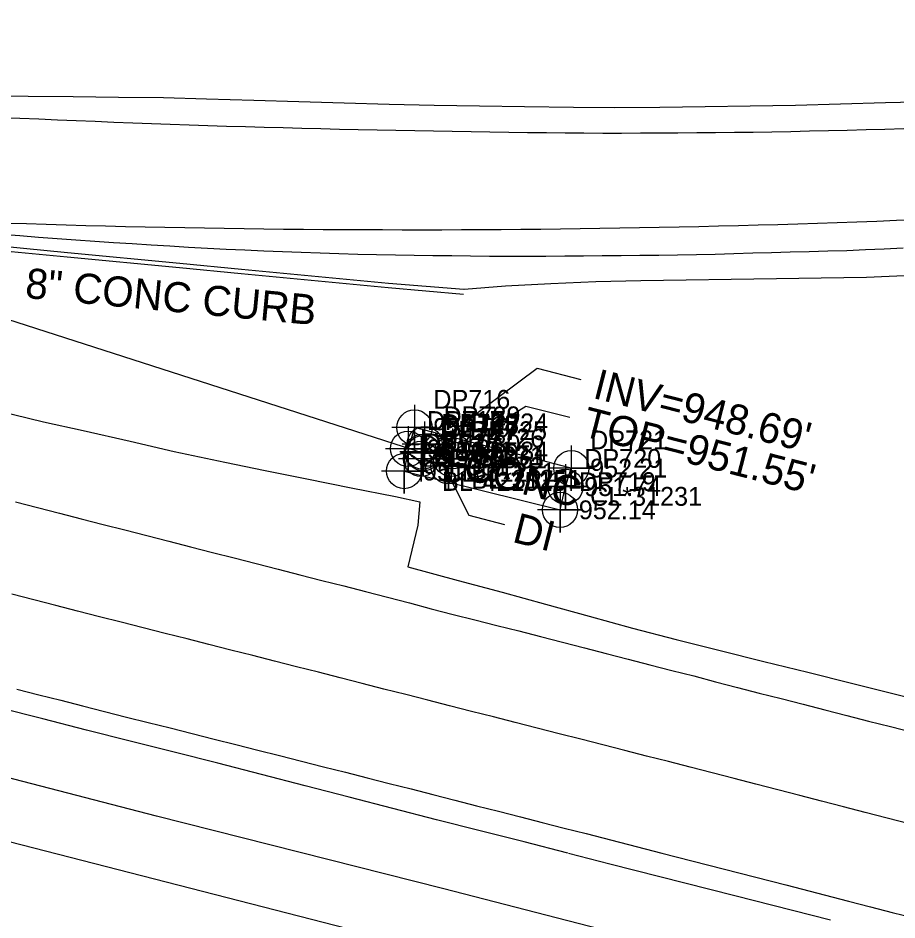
# Model space of a CAD drawing. Extents: x 1182322 to 1186765, y 572295 to 575411.
# Drawn here: x 1183843.1 to 1183959.9, y 574241.7 to 574361.5 of the extents above; entities that cross this region are included whole.
import ezdxf

# ---------------------------------------------------------------- set-up
doc = ezdxf.new("R2010")
doc.units = 0
for name, color, linetype in [('COGO Default Chain', 7, 'Continuous'), ('Exist Guardrail Cable Guide Rail', 7, 'Continuous'), ('Exist Horizontal Alignment', 7, 'Continuous'), ('Exist Right of Way Line', 7, 'Continuous'), ('Exist Roads Curbs', 7, 'Continuous'), ('Exist Roads Curbs Text', 7, 'Continuous'), ('Exist Roads EOP', 7, 'Continuous'), ('Exist Roads EOT', 7, 'Continuous'), ('Exist Structure Minor Drop Inlet', 7, 'Continuous'), ('Exist Structure Minor Drop Inlet Cogo Comment', 7, 'Continuous'), ('Exist Structure Minor Drop Inlet Cogo Elevation', 7, 'Continuous'), ('Exist Structure Minor Drop Inlet Cogo Number', 7, 'Continuous'), ('Exist Structure Minor Drop Inlet Cogo Point CELL', 7, 'Continuous'), ('Exist Structure Minor Drop Inlet Leader', 7, 'Continuous'), ('Exist Structure Minor Drop Inlet Text', 7, 'Continuous'), ('Exist Structure Minor Drop Inlet Top Elevation', 7, 'Continuous'), ('Exist Structure Minor Paved Ditch or Gutter', 7, 'Continuous'), ('Exist Structure Minor Paved Ditch or Gutter Cogo Comment', 7, 'Continuous'), ('Exist Structure Minor Paved Ditch or Gutter Cogo Elevation', 7, 'Continuous'), ('Exist Structure Minor Paved Ditch or Gutter Cogo Number', 7, 'Continuous'), ('Exist Structure Minor Paved Ditch or Gutter Cogo Point CELL', 7, 'Continuous'), ('Exist Structure Minor Paved Ditch or Gutter Text', 7, 'Continuous'), ('Exist Structure Minor Pipes RCP 15 Inch', 7, 'Continuous'), ('Exist Structure Minor Pipes RCP 15 Inch Cogo Comment', 7, 'Continuous'), ('Exist Structure Minor Pipes RCP 15 Inch Cogo Elevation', 7, 'Continuous'), ('Exist Structure Minor Pipes RCP 15 Inch Cogo Number', 7, 'Continuous'), ('Exist Structure Minor Pipes RCP 15 Inch Cogo Point CELL', 7, 'Continuous'), ('Exist Structure Minor Pipes RCP 15 Inch Invert', 7, 'Continuous'), ('Exist Structure Minor Pipes RCP 15 Inch Leader', 7, 'Continuous')]:
    doc.layers.add(name, color=color, linetype=linetype)

msp = doc.modelspace()

# ---------------------------------------------------------------- linework, layer by layer
at = {"layer": 'COGO Default Chain'}
msp.add_line((1182528.88, 574588.22), (1185362.14, 573862.9), dxfattribs=at)
msp.add_arc((1183895.74, 575980.86), 1647.48, 268.02702, 273.87461, dxfattribs=at)
at = {"layer": 'Exist Guardrail Cable Guide Rail'}
msp.add_lwpolyline([(1184319.91, 574138.28), (1184282.46, 574147.69), (1184244.64, 574157.75), (1184203.05, 574168.29), (1184172.8, 574176.06), (1184142.06, 574184.01), (1184109.94, 574191.89), (1184074.72, 574201.12), (1184044.07, 574208.88), (1184009.19, 574217.87), (1183971.3, 574227.52), (1183932.85, 574237.24), (1183899.52, 574245.85), (1183861.53, 574255.44), (1183824.79, 574264.96), (1183790.01, 574273.64), (1183748.12, 574284.29), (1183724.74, 574289.7)], dxfattribs=at)
at = {"layer": 'Exist Horizontal Alignment'}
msp.add_line((1182528.88, 574588.22), (1185362.14, 573862.9), dxfattribs=at)
msp.add_arc((1183895.74, 575980.86), 1647.48, 268.02702, 273.87461, dxfattribs=at)
at = {"layer": 'Exist Right of Way Line'}
msp.add_arc((1184007.06, 574337.15), 88, 93.8746, 93.8746, dxfattribs=at)
at = {"layer": 'Exist Roads Curbs'}
msp.add_lwpolyline([(1183902.3, 574324.77), (1183892.33, 574325.65), (1183872.78, 574327.5), (1183864.61, 574328.3), (1183849.69, 574329.72), (1183834.77, 574331.13), (1183819.84, 574332.33), (1183804.89, 574333.27), (1183789.92, 574334.14), (1183774.94, 574334.93), (1183759.95, 574336.05), (1183745, 574337.29), (1183730.04, 574338.48), (1183726.32, 574338.81)], dxfattribs=at)
at = {"layer": 'Exist Roads EOP'}
for points in [[(1183838.5, 574351.22), (1183844.49, 574351.12), (1183850.49, 574351.06), (1183856.49, 574351.01), (1183862.48, 574350.96), (1183868.2, 574350.79), (1183874.47, 574350.61), (1183880.47, 574350.42), (1183886.46, 574350.22), (1183892.45, 574350.04), (1183898.44, 574349.94), (1183904.44, 574349.86), (1183910.43, 574349.76), (1183916.93, 574349.67), (1183922.43, 574349.62), (1183928.42, 574349.66), (1183934.42, 574349.73), (1183940.41, 574349.83), (1183946.41, 574349.94), (1183952.39, 574350.11), (1183958.39, 574350.27), (1183964.39, 574350.43)], [(1183902.36, 574325.42), (1183892.38, 574326.25), (1183872.82, 574328.09), (1183864.66, 574328.89), (1183849.74, 574330.32), (1183834.82, 574331.77), (1183819.88, 574332.96), (1183804.93, 574333.9), (1183789.95, 574334.76), (1183774.98, 574335.56), (1183760, 574336.67), (1183745.06, 574337.91), (1183730.12, 574339.27), (1183726.56, 574339.59)], [(1183961.86, 574327.28), (1183955.87, 574327.03), (1183949.81, 574326.92), (1183943.88, 574326.84), (1183937.88, 574326.76), (1183931.89, 574326.68), (1183925.89, 574326.6), (1183919.89, 574326.44), (1183913.9, 574326.2), (1183907.91, 574325.86), (1183902.4, 574325.43)], [(1183840.52, 574309.3), (1183846.55, 574307.84), (1183851.8, 574306.68), (1183858.06, 574305.27), (1183863.91, 574303.93), (1183870.61, 574302.49), (1183875.96, 574301.4), (1183881.52, 574300.26), (1183887.4, 574299.06), (1183893.29, 574297.93), (1183896.51, 574297.21), (1183896.24, 574294.1), (1183894.91, 574288.6), (1183901.63, 574286.75), (1183907.44, 574285.24), (1183913.22, 574283.64), (1183919, 574282.04), (1183924.78, 574280.44), (1183930.58, 574278.92), (1183936.41, 574277.47), (1183942.23, 574276.02), (1183948.05, 574274.57), (1183953.87, 574273.13), (1183959.7, 574271.68), (1183965.51, 574270.19)], [(1183916.18, 574250.55), (1183910.37, 574252.03), (1183904.55, 574253.51), (1183898.74, 574254.99), (1183892.93, 574256.48), (1183887.12, 574257.98), (1183881.31, 574259.48), (1183875.5, 574260.98), (1183869.69, 574262.48), (1183863.88, 574263.96), (1183858.06, 574265.43), (1183852.24, 574266.9), (1183846.43, 574268.37), (1183840.61, 574269.83)], [(1183916.26, 574250.53), (1183921.74, 574249.13), (1183938.35, 574244.9), (1183951.05, 574241.67)]]:
    msp.add_lwpolyline(points, dxfattribs=at)
at = {"layer": 'Exist Roads EOT'}
for points in [[(1183840.9, 574348.31), (1183843.39, 574348.2), (1183845.89, 574348.1), (1183848.39, 574347.99), (1183850.88, 574347.88), (1183853.38, 574347.78), (1183855.88, 574347.68), (1183858.38, 574347.58), (1183860.87, 574347.49), (1183863.37, 574347.4), (1183865.87, 574347.31), (1183868.36, 574347.23), (1183870.86, 574347.15), (1183873.36, 574347.08), (1183875.86, 574347.01), (1183878.35, 574346.95), (1183880.85, 574346.88), (1183883.35, 574346.82), (1183885.85, 574346.76), (1183888.34, 574346.69), (1183890.84, 574346.64), (1183893.34, 574346.59), (1183895.84, 574346.55), (1183898.34, 574346.5), (1183900.83, 574346.46), (1183903.33, 574346.42), (1183905.83, 574346.38), (1183908.33, 574346.35), (1183910.83, 574346.31), (1183913.33, 574346.28), (1183915.82, 574346.25), (1183918.32, 574346.23), (1183920.82, 574346.21), (1183923.32, 574346.22), (1183925.82, 574346.23), (1183928.31, 574346.24), (1183930.81, 574346.26), (1183933.31, 574346.28), (1183935.81, 574346.3), (1183938.31, 574346.32), (1183940.81, 574346.35), (1183943.3, 574346.4), (1183945.8, 574346.45), (1183948.3, 574346.5), (1183950.8, 574346.56), (1183953.29, 574346.62), (1183955.79, 574346.69), (1183958.29, 574346.76), (1183960.79, 574346.84)], [(1183960.71, 574330.92), (1183958.22, 574330.81), (1183955.72, 574330.69), (1183953.23, 574330.59), (1183950.73, 574330.52), (1183948.23, 574330.45), (1183945.73, 574330.38), (1183943.24, 574330.31), (1183940.74, 574330.24), (1183938.24, 574330.17), (1183935.74, 574330.1), (1183933.25, 574330.03), (1183930.75, 574329.98), (1183928.25, 574329.96), (1183925.75, 574329.93), (1183923.25, 574329.91), (1183920.75, 574329.89), (1183918.25, 574329.87), (1183915.76, 574329.85), (1183913.26, 574329.83), (1183910.76, 574329.81), (1183908.26, 574329.8), (1183905.76, 574329.83), (1183903.26, 574329.86), (1183900.76, 574329.89), (1183898.26, 574329.92), (1183895.77, 574329.96), (1183893.27, 574330), (1183890.77, 574330.04), (1183888.27, 574330.09), (1183885.77, 574330.16), (1183883.28, 574330.24), (1183880.78, 574330.33), (1183878.28, 574330.43), (1183875.79, 574330.53), (1183873.29, 574330.64), (1183870.79, 574330.76), (1183868.3, 574330.88), (1183865.8, 574331.02), (1183863.31, 574331.17), (1183860.82, 574331.32), (1183858.32, 574331.48), (1183855.83, 574331.64), (1183853.34, 574331.8), (1183850.84, 574331.99), (1183848.35, 574332.17), (1183845.86, 574332.36), (1183843.37, 574332.55), (1183840.88, 574332.74)], [(1183842.82, 574297.21), (1183845.73, 574296.47), (1183848.64, 574295.73), (1183851.54, 574294.98), (1183854.45, 574294.23), (1183857.35, 574293.49), (1183860.26, 574292.74), (1183863.16, 574291.99), (1183866.07, 574291.25), (1183868.98, 574290.5), (1183871.88, 574289.76), (1183874.79, 574289.02), (1183877.7, 574288.28), (1183880.6, 574287.54), (1183883.51, 574286.79), (1183886.41, 574286.04), (1183889.32, 574285.29), (1183892.22, 574284.54), (1183895.13, 574283.78), (1183898.03, 574283.02), (1183900.93, 574282.27), (1183903.84, 574281.54), (1183906.75, 574280.8), (1183909.66, 574280.06), (1183912.56, 574279.32), (1183915.47, 574278.58), (1183918.38, 574277.83), (1183921.28, 574277.09), (1183924.19, 574276.33), (1183927.09, 574275.58), (1183929.99, 574274.83), (1183932.9, 574274.08), (1183935.8, 574273.32), (1183938.71, 574272.57), (1183941.61, 574271.82), (1183944.52, 574271.08), (1183947.42, 574270.33), (1183950.33, 574269.58), (1183953.24, 574268.84), (1183956.14, 574268.09), (1183959.05, 574267.35), (1183961.95, 574266.61)], [(1183961.5, 574254.44), (1183958.59, 574255.19), (1183955.69, 574255.94), (1183952.79, 574256.69), (1183949.88, 574257.44), (1183946.98, 574258.19), (1183944.07, 574258.95), (1183941.17, 574259.7), (1183938.26, 574260.45), (1183935.36, 574261.2), (1183932.45, 574261.95), (1183929.55, 574262.7), (1183926.64, 574263.44), (1183923.74, 574264.18), (1183920.83, 574264.93), (1183917.92, 574265.67), (1183915.02, 574266.41), (1183912.11, 574267.16), (1183909.2, 574267.9), (1183906.3, 574268.64), (1183903.39, 574269.38), (1183900.48, 574270.13), (1183897.58, 574270.87), (1183894.67, 574271.61), (1183891.76, 574272.35), (1183888.86, 574273.09), (1183885.95, 574273.83), (1183883.04, 574274.57), (1183880.13, 574275.31), (1183877.23, 574276.05), (1183874.32, 574276.79), (1183871.41, 574277.53), (1183868.5, 574278.27), (1183865.6, 574279), (1183862.69, 574279.74), (1183859.78, 574280.48), (1183856.87, 574281.22), (1183853.97, 574281.96), (1183851.06, 574282.7), (1183848.15, 574283.44), (1183845.25, 574284.2), (1183842.34, 574284.96)], [(1183843, 574272.32), (1183845.91, 574271.59), (1183848.82, 574270.85), (1183851.73, 574270.11), (1183854.63, 574269.37), (1183857.54, 574268.63), (1183860.45, 574267.9), (1183863.36, 574267.17), (1183866.27, 574266.43), (1183869.18, 574265.7), (1183872.09, 574264.97), (1183875, 574264.23), (1183877.9, 574263.5), (1183880.81, 574262.76), (1183883.72, 574262.02), (1183886.63, 574261.28), (1183889.54, 574260.55), (1183892.44, 574259.81), (1183895.35, 574259.07), (1183898.26, 574258.33), (1183901.16, 574257.58), (1183904.07, 574256.84), (1183906.98, 574256.1), (1183909.88, 574255.36), (1183912.79, 574254.62), (1183915.7, 574253.88), (1183918.61, 574253.13)], [(1183918.61, 574253.13), (1183928.66, 574250.54), (1183945.12, 574246.31), (1183953.44, 574244.17)], [(1183953.47, 574244.16), (1183956.38, 574243.42), (1183959.28, 574242.67), (1183962.19, 574241.93)]]:
    msp.add_lwpolyline(points, dxfattribs=at)
at = {"layer": 'Exist Structure Minor Drop Inlet'}
msp.add_lwpolyline([(1183900.84, 574303.96), (1183900.69, 574302.92), (1183900.32, 574301.96), (1183896.69, 574302.94), (1183896.88, 574303.88), (1183897.16, 574304.9), (1183900.84, 574303.96)], dxfattribs=at)
at = {"layer": 'Exist Structure Minor Drop Inlet Cogo Point CELL'}
for points in [[(1183896.88, 574306.88), (1183896.88, 574300.88), (1183896.88, 574303.88), (1183899.88, 574303.88), (1183893.88, 574303.88)], [(1183897.16, 574307.9), (1183897.16, 574301.9), (1183897.16, 574304.9), (1183900.16, 574304.9), (1183894.16, 574304.9)], [(1183900.84, 574306.96), (1183900.84, 574300.96), (1183900.84, 574303.96), (1183903.84, 574303.96), (1183897.84, 574303.96)], [(1183896.69, 574305.94), (1183896.69, 574299.94), (1183896.69, 574302.94), (1183899.69, 574302.94), (1183893.69, 574302.94)], [(1183900.69, 574305.92), (1183900.69, 574299.92), (1183900.69, 574302.92), (1183903.69, 574302.92), (1183897.69, 574302.92)], [(1183900.32, 574304.96), (1183900.32, 574298.96), (1183900.32, 574301.96), (1183903.32, 574301.96), (1183897.32, 574301.96)]]:
    msp.add_lwpolyline(points, dxfattribs=at)
for centre in [(1183897.16, 574304.9), (1183896.88, 574303.88), (1183900.84, 574303.96), (1183896.69, 574302.94), (1183900.69, 574302.92), (1183900.32, 574301.96)]:
    msp.add_circle(centre, 2.34, dxfattribs=at)
at = {"layer": 'Exist Structure Minor Drop Inlet Leader'}
for points in [[(1183899.65, 574303.15), (1183910.62, 574309.93), (1183916.43, 574308.45)], [(1183899.48, 574302.46), (1183903.03, 574295.44), (1183907.76, 574294.23)]]:
    msp.add_lwpolyline(points, dxfattribs=at)
at = {"layer": 'Exist Structure Minor Paved Ditch or Gutter'}
msp.add_lwpolyline([(1183895.81, 574307.09), (1183894.96, 574304.27), (1183894.44, 574301.31), (1183915.14, 574296.16), (1183915.86, 574299.24), (1183916.64, 574301.7), (1183895.81, 574307.09)], dxfattribs=at)
at = {"layer": 'Exist Structure Minor Paved Ditch or Gutter Cogo Point CELL'}
for points in [[(1183895.81, 574310.09), (1183895.81, 574304.09), (1183895.81, 574307.09), (1183898.81, 574307.09), (1183892.81, 574307.09)], [(1183894.96, 574307.27), (1183894.96, 574301.27), (1183894.96, 574304.27), (1183897.96, 574304.27), (1183891.96, 574304.27)], [(1183916.64, 574304.7), (1183916.64, 574298.7), (1183916.64, 574301.7), (1183919.64, 574301.7), (1183913.64, 574301.7)], [(1183894.44, 574304.31), (1183894.44, 574298.31), (1183894.44, 574301.31), (1183897.44, 574301.31), (1183891.44, 574301.31)], [(1183915.86, 574302.24), (1183915.86, 574296.24), (1183915.86, 574299.24), (1183918.86, 574299.24), (1183912.86, 574299.24)], [(1183915.14, 574299.16), (1183915.14, 574293.16), (1183915.14, 574296.16), (1183918.14, 574296.16), (1183912.14, 574296.16)]]:
    msp.add_lwpolyline(points, dxfattribs=at)
for centre in [(1183895.81, 574307.09), (1183894.96, 574304.27), (1183894.44, 574301.31), (1183916.64, 574301.7), (1183915.86, 574299.24), (1183915.14, 574296.16)]:
    msp.add_circle(centre, 2.34, dxfattribs=at)
at = {"layer": 'Exist Structure Minor Pipes RCP 15 Inch'}
msp.add_line((1183896.97, 574303.68), (1183633.81, 574388.32), dxfattribs=at)
at = {"layer": 'Exist Structure Minor Pipes RCP 15 Inch Cogo Point CELL'}
msp.add_lwpolyline([(1183896.97, 574306.68), (1183896.97, 574300.68), (1183896.97, 574303.68), (1183899.97, 574303.68), (1183893.97, 574303.68)], dxfattribs=at)
msp.add_circle((1183896.97, 574303.68), 2.34, dxfattribs=at)
at = {"layer": 'Exist Structure Minor Pipes RCP 15 Inch Leader'}
msp.add_lwpolyline([(1183896.97, 574303.68), (1183912.09, 574314.97), (1183917.91, 574313.49)], dxfattribs=at)

# ---------------------------------------------------------------- texts
at = {"layer": 'Exist Roads Curbs Text'}
msp.add_text('8" CONC CURB', height=4, rotation=354.6047, dxfattribs=at).set_placement((1183844, 574324.33))
at = {"layer": 'Exist Structure Minor Drop Inlet Cogo Comment'}
for s, p in [('CL*31251', (1183899.66, 574299.9)), ('BL*31251', (1183903.34, 574298.96))]:
    msp.add_text(s, height=2.5, dxfattribs=at).set_placement(p)
at = {"layer": 'Exist Structure Minor Drop Inlet Cogo Elevation'}
for s, p in [('951.80', (1183899.66, 574303.65)), ('951.55', (1183899.38, 574302.62)), ('951.84', (1183903.34, 574302.71)), ('951.65', (1183899.19, 574301.69)), ('951.72', (1183902.82, 574300.71)), ('951.61', (1183903.19, 574301.67))]:
    msp.add_text(s, height=2.5, dxfattribs=at).set_placement(p)
at = {"layer": 'Exist Structure Minor Drop Inlet Cogo Number'}
for s, p in [('DP729', (1183899.66, 574307.4)), ('DP727', (1183899.19, 574305.44)), ('DP728', (1183899.38, 574306.38)), ('DP725', (1183903.19, 574305.42)), ('DP724', (1183903.34, 574306.46)), ('DP726', (1183902.82, 574304.46))]:
    msp.add_text(s, height=2.5, dxfattribs=at).set_placement(p)
at = {"layer": 'Exist Structure Minor Drop Inlet Text'}
msp.add_text('DI', height=4, rotation=345.6405, dxfattribs=at).set_placement((1183908.66, 574291.93))
at = {"layer": 'Exist Structure Minor Drop Inlet Top Elevation'}
msp.add_text("TOP=951.55'", height=4, rotation=345.6405, dxfattribs=at).set_placement((1183917.87, 574306.01))
at = {"layer": 'Exist Structure Minor Paved Ditch or Gutter Cogo Comment'}
for s, p in [('BL*31231', (1183898.31, 574302.09)), ('CL*31231', (1183919.14, 574296.7))]:
    msp.add_text(s, height=2.5, dxfattribs=at).set_placement(p)
at = {"layer": 'Exist Structure Minor Paved Ditch or Gutter Cogo Elevation'}
for s, p in [('952.09', (1183898.31, 574305.84)), ('951.86', (1183897.46, 574303.02)), ('951.96', (1183896.94, 574300.06)), ('952.21', (1183919.14, 574300.45)), ('951.74', (1183918.36, 574297.99)), ('952.14', (1183917.64, 574294.91))]:
    msp.add_text(s, height=2.5, dxfattribs=at).set_placement(p)
at = {"layer": 'Exist Structure Minor Paved Ditch or Gutter Cogo Number'}
for s, p in [('DP716', (1183898.31, 574309.59)), ('DP717', (1183897.46, 574306.77)), ('DP718', (1183896.94, 574303.81)), ('DP721', (1183919.14, 574304.2)), ('DP720', (1183918.36, 574301.74)), ('DP719', (1183917.64, 574298.66))]:
    msp.add_text(s, height=2.5, dxfattribs=at).set_placement(p)
at = {"layer": 'Exist Structure Minor Paved Ditch or Gutter Text'}
msp.add_text('CONC', height=4, rotation=345.6405, dxfattribs=at).set_placement((1183902.07, 574300.32))
at = {"layer": 'Exist Structure Minor Pipes RCP 15 Inch Cogo Comment'}
msp.add_text('BL*421515', height=2.5, dxfattribs=at).set_placement((1183899.47, 574298.68))
at = {"layer": 'Exist Structure Minor Pipes RCP 15 Inch Cogo Elevation'}
msp.add_text('948.69', height=2.5, dxfattribs=at).set_placement((1183899.47, 574302.43))
at = {"layer": 'Exist Structure Minor Pipes RCP 15 Inch Cogo Number'}
msp.add_text('DP715', height=2.5, dxfattribs=at).set_placement((1183899.47, 574306.18))
at = {"layer": 'Exist Structure Minor Pipes RCP 15 Inch Invert'}
msp.add_text("INV=948.69'", height=4, rotation=345.6405, dxfattribs=at).set_placement((1183919.35, 574311.05))

doc.saveas('drawing.dxf')
